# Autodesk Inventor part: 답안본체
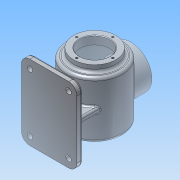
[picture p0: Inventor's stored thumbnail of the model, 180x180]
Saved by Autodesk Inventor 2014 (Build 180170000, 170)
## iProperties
Created: 2016-09
Part Number: 답안본체
Material: 알루미늄 6061
Document SubType Name: 판금
Designer: net
Density: 2.71 g/cm^3
Sheet Metal Rule: 기본값
Appearance: 알루미늄 - 평지
Mass: 987.813 g
Surface Area: 1285.9 cm^2
Volume: 364.507 cm^3
Author: net
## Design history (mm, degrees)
sketch "스케치3"
  geometry: L1 (0, 0)-(38, 0); L2 (0, -122)-(0, 0); L3 (38, 0)-(38, -12); L4 (38, -12)-(50, -12); L5 (50, -12)-(50, -112); A1 r 115 centre (3.008, -7.039) between (0, -122) and (50, -112)
  constraints: 10 end point, 2 parallel, 2 point on circle, 1 centre point, 1 horizontal, 1 perpendicular
  dimensions: "d18" = 122 distance from line of L2.start L1; "d24" = 100 diameter of L5 L2; "d25" = 76 diameter of L3 L2; "d26" = 122 distance of L2.start L1.start; "d30" = 110 distance from line of L4 L2.start; "d31" = 115 radius of A1; "d33" = 100 distance of L4.end L5.end
revolve "회전1" sketch "스케치3" stored, may be unused: angle "d27" = 90 deg
fillet "모깎기1" dims "d28" = 5
sketch "스케치4"
  geometry: 1 further point
node "작업 평면1"
node "작업 평면3"
  node "작업 평면2"
sketch "스케치6"
  geometry: L1 (-50, -72)-(50, -72); L2 (50, -72)-(50, -82); L3 (50, -82)-(-50, -82); L4 (-50, -82)-(-50, -72); L5 (0, 0)-(0, -82); 1 further point
  constraints: 10 end point, 2 midpoint, 2 parallel, 2 perpendicular, 1 horizontal, 1 point on line
  dimensions: "d43" = 10 distance of L1.end L2.end; "d44" = 100 distance of L2.end L3.end; "d81" = 82 distance from line of L3 L5.start
extrude "돌출2" join sketch "스케치6" distance "d46" = 135; taper "d47" = 0 deg
fillet "모깎기4" dims "d48" = 15
fillet "모깎기5" dims "d49" = 3
hole "구멍1" diameter "d52" = 10; stored, may be unused: countersink angle "d56" = 90 deg, drill point angle "d58" = 118 deg; dims "d50" = 10, "d51" = 10, "d53" = 6, "d54" = 4, "d55" = 2, "d57" = 0.5 (derived)
sketch "스케치8"
  geometry: L1 (0, 0)-(70, 0) reference; L2 (-12, -117)-(-12, -12) reference; L3 (70, -129)-(0, -129) reference; L4 (82, -12)-(82, -117) reference; L5 (30, -24.5)-(40, -24.5); L6 (40, -24.5)-(40, -104.5); L7 (40, -104.5)-(30, -104.5); L8 (30, -104.5)-(30, -24.5); L9 (-12, -64.5)-(82, -64.5); L10 (35, 0)-(35, -129); 1 further point
  constraints: 12 end point, 4 midpoint, 2 parallel, 1 horizontal, 1 perpendicular
  dimensions: "d59" = 40 distance between parallel lines of L9 L5; "d60" = 40 distance between parallel lines of L7 L9; "d61" = 10 distance between parallel lines of L6 L8; "d62" = 5 distance between parallel lines of L10 L8
extrude "돌출3" join sketch "스케치8" distance "d63" = 100; taper "d64" = 0 deg
feature "면 기울기1" dims angle "d65" = 5 deg
feature "면 기울기2" dims angle "d66" = 5 deg
node "작업 평면4"
sketch "스케치9"
  geometry: L1 (-40, -16.712)-(40, -16.712); L2 (40, -16.712)-(40, -72); L3 (40, -72)-(-40, -72); L4 (-40, -72)-(-40, -16.712); L5 (-35, -72)-(35, -72) reference; C1 r 50 at (0, 0) reference; 1 further point
  constraints: 8 end point, 2 parallel, 1 horizontal, 1 perpendicular
  dimensions: "d67" = 0 distance between parallel lines of L5 L3; "d68" = 40 distance from line of point (0, 0) L4; "d69" = 40 distance from line of L2 point (0, 0); "d70" = 55.28833 distance between parallel lines of L3 L1
extrude "돌출4" join sketch "스케치9" stored distance "d71" = 10; taper "d72" = 0 deg
node "작업 평면5"
sketch "스케치10"
  geometry: L1 (85, -22.5)-(-15, -22.5) reference; L2 (81.909, -118.83)-(-11.909, -118.83) reference; L3 (35, -22.5)-(35, -118.83); L4 (-10, -17.5)-(80, -17.5) reference; C1 r 38 at (35, -67.5); 1 further point
  constraints: 2 end point, 2 midpoint, 1 centre point, 1 point on line
  dimensions: "d77" = 76 diameter of C1; "d78" = 50 distance from line of L4 C1.centre
extrude "돌출5" join sketch "스케치10" stored distance "d79" = 10; taper "d80" = 0 deg
fillet "모깎기7" dims "d82" = 3
node "작업 평면6"
sketch "스케치15" dims "d86" = 65
  geometry: L1 (0, 0)-(0, 32.5); C1 r 38 at (0, 0) reference; 2 further points
  constraints: 2 coincident, 2 end point, 1 vertical, 1 vertical alignment, 2 other
hole "구멍2" sketch "스케치15" at (0, 32.5) diameter "d87" = 4; stored, may be unused: countersink angle "d91" = 90 deg, drill point angle "d93" = 118 deg; dims "d88" = 6, "d89" = 4, "d90" = 2, "d92" = 10
feature "스레드1" dims "d94" = 8, "d95" = 0
sketch "스케치16" dims "d99" = 65
  geometry: L1 (0, 0)-(0, 32.5); C1 r 38 at (0, 0) reference; 1 further point
  constraints: 2 coincident, 2 end point, 1 vertical, 1 vertical alignment, 2 other
hole "구멍3" sketch "스케치16" at (0, 32.5) diameter "d100" = 4; stored, may be unused: countersink angle "d104" = 90 deg, drill point angle "d106" = 118 deg; dims "d101" = 6, "d102" = 4, "d103" = 2, "d105" = 10
feature "스레드2" dims "d107" = 8, "d108" = 0
node "작업 평면7"
sketch "스케치18"
  geometry: C1 r 38 at (0, 0) reference; C2 r 27 at (0, 0)
  constraints: 1 centre point, 1 coincident
  dimensions: "d119" = 54 diameter of C2
extrude "돌출6" cut sketch "스케치18" distance "d120" = 15; taper "d121" = 0 deg
sketch "스케치20"
  geometry: C1 r 38 at (0, 0) reference; C2 r 27 at (0, 0); 1 further point
  constraints: 1 centre point, 1 coincident
  dimensions: "d122" = 54 diameter of C2
extrude "돌출7" cut sketch "스케치20" distance "d123" = 50; taper "d124" = 0 deg
node "작업 평면8"
sketch "스케치21"
  geometry: C1 r 47 at (0, 0); 1 further point
  constraints: 1 centre point, 1 coincident
  dimensions: "d126" = 94 diameter of C1
extrude "돌출8" cut sketch "스케치21" stored distance "d127" = 94; taper "d128" = 0 deg
sketch "스케치22"
  geometry: 1 further point
sketch "스케치23"
  geometry: L1 (46.909, -113.33)-(-46.909, -113.33) reference; L2 (-47, -109)-(47, -109) reference; L3 (0, -122)-(0, -109); L4 (0, -119.163)-(0, -109); L5 (47, -109)-(0, -109); A1 r 115 centre (3.008, -7.039) between (3.008, -122.039) and (46.909, -113.33) reference; A2 r 5 centre (45, -108.709) between (46.909, -113.33) and (50, -108.709) reference; A3 r 112 centre (0.38, -7.164) between (0, -119.163) and (47, -109); 1 further point
  constraints: 6 end point, 2 collinear, 2 point on circle, 1 centre point, 1 midpoint, 1 point on line
  dimensions: "d129" = 112 radius of A3; "d130" = 0.12463 vertical distance of A1.centre A3.centre
revolve "회전2" sketch "스케치23" stored, may be unused: angle "d131" = 90 deg
fillet "모깎기8" dims "d132" = 2
chamfer "모따기1" distance "d133" = 1; stored, may be unused: second distance "d134" = 2, angle "d135" = 45 deg
chamfer "모따기2" distance "d136" = 1; stored, may be unused: second distance "d137" = 2, angle "d138" = 45 deg
fillet "모깎기9" dims "d139" = 3, "d140" = 3
fillet "모깎기10" dims "d141" = 3
node "솔리드1"
mirror "대칭1"
mirror "대칭2"
pattern_circular "원형 패턴1" dims angle "d97" = 360 deg
pattern_circular "원형 패턴2" dims angle "d110" = 360 deg
node "투영된 루프1"
other parameters: "K계수" = 4.4, "BendRadius" = 0.5 (derived), "BendReliefWidth" = 0.5 (derived), "BendReliefDepth" = 0.25 (derived), "CornerReliefSize" = 2 (derived), "SeamGap" = 0.01, "MinimumRemnant" = 1 (derived), "TransitionRadius" = 0.5 (= BendRadius), "d34" = -82, "d42" = 67.5, "d76" = -147, "d85" = -122
